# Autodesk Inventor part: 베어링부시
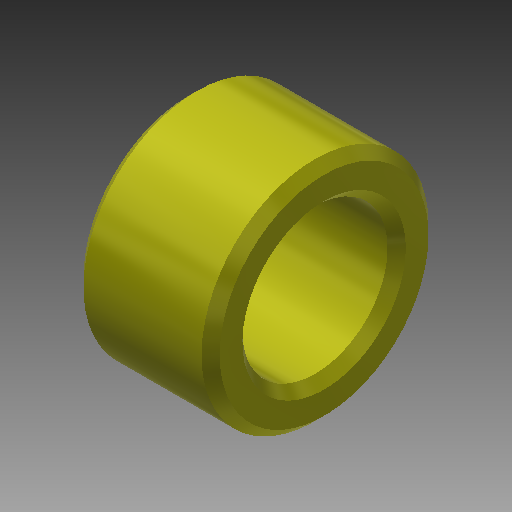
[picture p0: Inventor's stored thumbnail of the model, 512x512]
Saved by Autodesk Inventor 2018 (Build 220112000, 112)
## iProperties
Created: 2019-03
Part Number: 베어링부시
Material: 강철, 연강
Document SubType Name: Modeling
Designer: mduedu
Density: 1 g/cm^3
Appearance: 노란색
Author: mduedu
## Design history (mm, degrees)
sketch "스케치1"
  geometry: L1 (-7.5, 12.5)-(7.5, 12.5); L2 (7.5, 12.5)-(7.5, 8); L3 (7.5, 8)-(-7.5, 8); L4 (-7.5, 8)-(-7.5, 12.5); L5 (-7.5, 0)-(7.5, 0); 3 further points
  constraints: 10 end point, 2 midpoint, 2 parallel, 2 perpendicular, 2 vertical alignment, 1 coincident, 1 horizontal
  dimensions: "d0" = 16 diameter of L3 L5; "d2" = 25 diameter of L1 L5; "d3" = 15 distance of L1.start L1.end
revolve "회전1" sketch "스케치1" stored, may be unused: angle "d4" = 90 deg
chamfer "모따기1" distance "d5" = 1; stored, may be unused: second distance "d6" = 2, angle "d7" = 45 deg
chamfer "모따기2" distance "d8" = 1; stored, may be unused: second distance "d9" = 2, angle "d10" = 45 deg
node "솔리드1"
